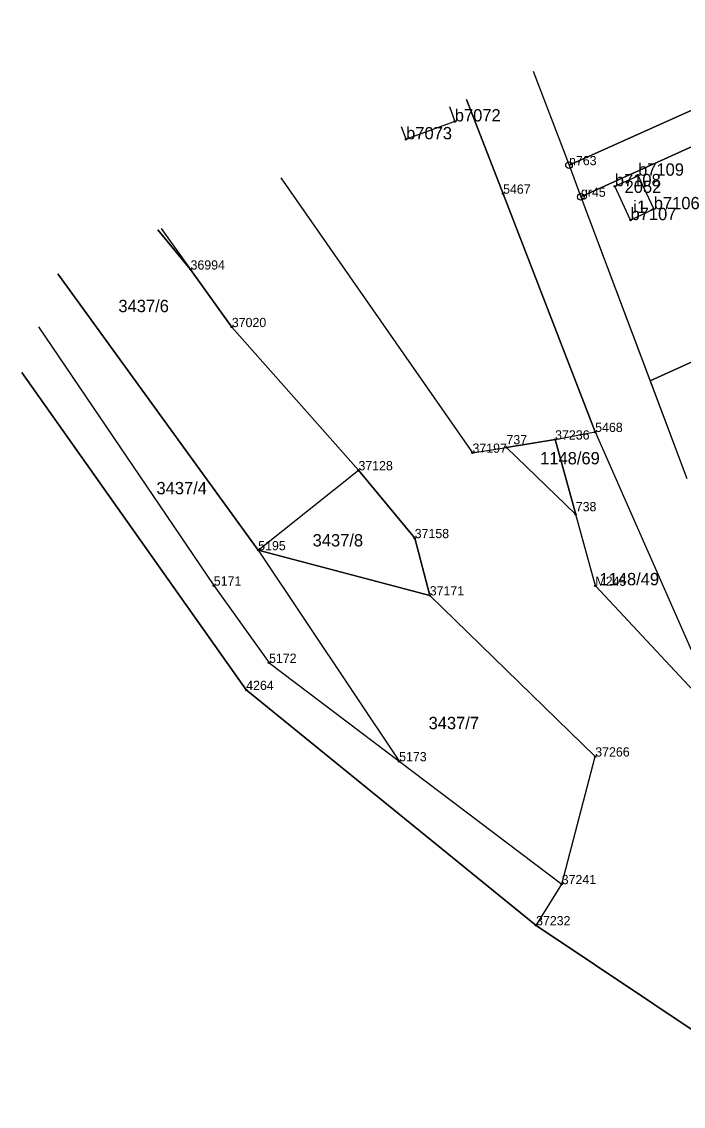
# Model space of a CAD drawing. Extents: x 7492083 to 7492670, y 5466693 to 5467065.
# Drawn here: x 7492083.3 to 7492163.8, y 5466933.4 to 5467065.4 of the extents above; entities that cross this region are included whole.
import ezdxf

# ---------------------------------------------------------------- set-up
doc = ezdxf.new("R2010")
doc.units = 0
for name, color, linetype in [('202-punkt graniczny', 7, 'Continuous'), ('202-punkt graniczny-Atr103', 7, 'Continuous'), ('203-punkt graniczny', 7, 'Continuous'), ('203-punkt graniczny-Atr103', 7, 'Continuous'), ('211-numer działki ewidencyjnej', 7, 'Continuous'), ('217-kontur klasyfikacyjny', 7, 'Continuous'), ('218-kontur użytku gruntowego', 7, 'Continuous'), ('219-działka ewidencyjna', 7, 'Continuous'), ('312-budynek ewidencyjny', 7, 'Continuous'), ('312-oznaczenie budynku ewidencyjnego', 7, 'Continuous'), ('312-oznaczenie budynku ewidencyjnego-Atr117', 7, 'Continuous'), ('Punkt budynku', 7, 'Continuous'), ('Punkt budynku-Atr103', 7, 'Continuous')]:
    doc.layers.add(name, color=color, linetype=linetype)

# ---------------------------------------------------------------- blocks, each defined once
blk = doc.blocks.new('203')
blk.add_circle((0, 0), 0.09)
blk = doc.blocks.new('202')
blk.add_circle((0, 0), 0.4)
blk = doc.blocks.new('PUNKTBUD')
blk.add_circle((0, 0), 0.09)

msp = doc.modelspace()

# ---------------------------------------------------------------- linework, layer by layer
at = {"layer": '217-kontur klasyfikacyjny'}
for points in [[(7492188.79, 5467065.38), (7492149.89, 5467047.92)], [(7492151.34, 5467044.08), (7492178.86, 5467056.54)], [(7492149.89, 5467047.92), (7492151.34, 5467044.08)], [(7492188.7, 5467034.81), (7492159.74, 5467021.69)], [(7492159.74, 5467021.69), (7492164.2, 5467009.8)]]:
    msp.add_lwpolyline(points, dxfattribs=at)
at = {"layer": '218-kontur użytku gruntowego'}
for points in [[(7492149.89, 5467047.92), (7492188.79, 5467065.38)], [(7492145.51, 5467059.36), (7492149.89, 5467047.92)], [(7492178.86, 5467056.54), (7492151.34, 5467044.08)], [(7492141.87, 5467044.45), (7492137.41, 5467055.93)], [(7492149.89, 5467047.92), (7492151.34, 5467044.08)], [(7492114.86, 5467046.38), (7492138.15, 5467012.93)], [(7492153.07, 5467015.46), (7492141.87, 5467044.45)], [(7492151.34, 5467044.08), (7492159.74, 5467021.69)], [(7492103.86, 5467035.22), (7492099.9, 5467040.05)], [(7492112.09, 5467001.07), (7492087.71, 5467034.69)], [(7492108.88, 5467028.22), (7492103.86, 5467035.22)], [(7492159.74, 5467021.69), (7492188.7, 5467034.81)], [(7492085.36, 5467028.26), (7492106.69, 5466996.76)], [(7492124.28, 5467010.8), (7492108.88, 5467028.22)], [(7492110.63, 5466984.07), (7492083.33, 5467022.7)], [(7492159.74, 5467021.69), (7492164.2, 5467009.8)], [(7492142.28, 5467013.59), (7492148.2, 5467014.54)], [(7492148.2, 5467014.54), (7492153.07, 5467015.46)], [(7492150.71, 5467005.43), (7492148.2, 5467014.54)], [(7492138.15, 5467012.93), (7492142.28, 5467013.59)], [(7492131.12, 5467002.54), (7492124.28, 5467010.8)], [(7492153.1, 5466996.74), (7492150.71, 5467005.43)], [(7492132.95, 5466995.57), (7492131.12, 5467002.54)], [(7492132.95, 5466995.57), (7492112.09, 5467001.07)], [(7492106.69, 5466996.76), (7492113.41, 5466987.37)], [(7492175.28, 5466972.96), (7492153.1, 5466996.74)], [(7492153.08, 5466975.97), (7492132.95, 5466995.57)], [(7492113.41, 5466987.37), (7492129.23, 5466975.39)], [(7492145.88, 5466955.43), (7492110.63, 5466984.07)], [(7492149, 5466960.44), (7492153.08, 5466975.97)], [(7492129.23, 5466975.39), (7492149, 5466960.44)], [(7492145.88, 5466955.43), (7492149, 5466960.44)], [(7492203.36, 5466916.98), (7492145.88, 5466955.43)]]:
    msp.add_lwpolyline(points, dxfattribs=at)
at = {"layer": '219-działka ewidencyjna'}
for points in [[(7492149.89, 5467047.92), (7492188.79, 5467065.38)], [(7492145.51, 5467059.36), (7492149.89, 5467047.92)], [(7492151.34, 5467044.08), (7492178.86, 5467056.54)], [(7492137.41, 5467055.93), (7492141.87, 5467044.45)], [(7492149.89, 5467047.92), (7492151.34, 5467044.08)], [(7492114.86, 5467046.38), (7492138.15, 5467012.93)], [(7492141.87, 5467044.45), (7492153.07, 5467015.46)], [(7492151.34, 5467044.08), (7492164.2, 5467009.8)], [(7492099.9, 5467040.05), (7492103.86, 5467035.22)], [(7492100.28, 5467040.21), (7492103.86, 5467035.22)], [(7492087.71, 5467034.69), (7492112.09, 5467001.07)], [(7492103.86, 5467035.22), (7492108.88, 5467028.22)], [(7492085.36, 5467028.26), (7492106.69, 5466996.76)], [(7492108.88, 5467028.22), (7492124.28, 5467010.8)], [(7492083.33, 5467022.7), (7492110.63, 5466984.07)], [(7492148.2, 5467014.54), (7492142.28, 5467013.59)], [(7492148.2, 5467014.54), (7492153.07, 5467015.46)], [(7492148.2, 5467014.54), (7492150.71, 5467005.43)], [(7492153.07, 5467015.46), (7492165.07, 5466988.24)], [(7492138.15, 5467012.93), (7492142.28, 5467013.59)], [(7492142.28, 5467013.59), (7492150.71, 5467005.43)], [(7492112.09, 5467001.07), (7492124.28, 5467010.8)], [(7492124.28, 5467010.8), (7492131.12, 5467002.54)], [(7492153.1, 5466996.74), (7492150.71, 5467005.43)], [(7492131.12, 5467002.54), (7492132.95, 5466995.57)], [(7492112.09, 5467001.07), (7492129.23, 5466975.39)], [(7492112.09, 5467001.07), (7492132.95, 5466995.57)], [(7492106.69, 5466996.76), (7492113.41, 5466987.37)], [(7492153.1, 5466996.74), (7492175.28, 5466972.96)], [(7492132.95, 5466995.57), (7492153.08, 5466975.97)], [(7492113.41, 5466987.37), (7492129.23, 5466975.39)], [(7492110.63, 5466984.07), (7492145.88, 5466955.43)], [(7492149, 5466960.44), (7492153.08, 5466975.97)], [(7492129.23, 5466975.39), (7492149, 5466960.44)], [(7492145.88, 5466955.43), (7492149, 5466960.44)], [(7492145.88, 5466955.43), (7492203.36, 5466916.98)]]:
    msp.add_lwpolyline(points, dxfattribs=at)
at = {"layer": '312-budynek ewidencyjny'}
for points in [[(7492135.34, 5467055.05), (7492136, 5467053.24)], [(7492130.08, 5467051.07), (7492129.53, 5467052.59)], [(7492136, 5467053.24), (7492130.08, 5467051.07)], [(7492155.46, 5467045.36), (7492158.29, 5467046.64)], [(7492158.29, 5467046.64), (7492160.2, 5467042.56)], [(7492157.37, 5467041.24), (7492155.46, 5467045.36)], [(7492160.2, 5467042.56), (7492157.37, 5467041.24)]]:
    msp.add_lwpolyline(points, dxfattribs=at)

# ---------------------------------------------------------------- block references
at = {"layer": '202-punkt graniczny'}
for p in [(7492149.89, 5467047.92), (7492151.34, 5467044.08)]:
    msp.add_blockref('202', p, dxfattribs=at)
at = {"layer": '203-punkt graniczny'}
for p in [(7492141.87, 5467044.45), (7492103.86, 5467035.22), (7492108.88, 5467028.22), (7492153.07, 5467015.46), (7492148.2, 5467014.54), (7492138.15, 5467012.93), (7492142.28, 5467013.59), (7492124.28, 5467010.8), (7492150.71, 5467005.43), (7492131.12, 5467002.54), (7492112.09, 5467001.07), (7492106.69, 5466996.76), (7492153.1, 5466996.74), (7492132.95, 5466995.57), (7492113.41, 5466987.37), (7492110.63, 5466984.07), (7492153.08, 5466975.97), (7492129.23, 5466975.39), (7492149, 5466960.44), (7492145.88, 5466955.43)]:
    msp.add_blockref('203', p, dxfattribs=at)
at = {"layer": 'Punkt budynku'}
for p in [(7492136, 5467053.24), (7492130.08, 5467051.07), (7492158.29, 5467046.64), (7492155.46, 5467045.36), (7492160.2, 5467042.56), (7492157.37, 5467041.24)]:
    msp.add_blockref('PUNKTBUD', p, dxfattribs=at)

# ---------------------------------------------------------------- texts
at = {"layer": '202-punkt graniczny-Atr103'}
for s, p in [('n763', (7492149.89, 5467047.92)), ('gr45', (7492151.34, 5467044.08))]:
    msp.add_text(s, height=1.125, dxfattribs=at).set_placement(p)
at = {"layer": '203-punkt graniczny-Atr103'}
for s, p in [('5467', (7492141.87, 5467044.45)), ('36994', (7492103.86, 5467035.22)), ('37020', (7492108.88, 5467028.22)), ('37236', (7492148.2, 5467014.54)), ('5468', (7492153.07, 5467015.46)), ('737', (7492142.28, 5467013.96)), ('37197', (7492138.15, 5467012.93)), ('37128', (7492124.28, 5467010.8)), ('738', (7492150.71, 5467005.81)), ('37158', (7492131.12, 5467002.54)), ('5195', (7492112.09, 5467001.07)), ('5171', (7492106.69, 5466996.76)), ('M245', (7492153.1, 5466996.74)), ('37171', (7492132.95, 5466995.57)), ('5172', (7492113.41, 5466987.37)), ('4264', (7492110.63, 5466984.07)), ('5173', (7492129.23, 5466975.39)), ('37266', (7492153.08, 5466975.97)), ('37241', (7492149, 5466960.44)), ('37232', (7492145.88, 5466955.43))]:
    msp.add_text(s, height=1.125, dxfattribs=at).set_placement(p)
at = {"layer": '211-numer działki ewidencyjnej'}
for s, p in [('3437/6', (7492095.09, 5467030.04)), ('1148/69', (7492146.38, 5467011.52)), ('3437/4', (7492099.72, 5467007.88)), ('3437/8', (7492118.71, 5467001.53)), ('1148/49', (7492153.59, 5466996.81)), ('3437/7', (7492132.81, 5466979.3))]:
    msp.add_text(s, height=1.5, dxfattribs=at).set_placement(p)
at = {"layer": '312-oznaczenie budynku ewidencyjnego'}
msp.add_text('2052', height=1.5, dxfattribs=at).set_placement((7492156.65, 5467044.55))
at = {"layer": '312-oznaczenie budynku ewidencyjnego-Atr117'}
msp.add_text('i1', height=1.5, dxfattribs=at).set_placement((7492157.7, 5467042.12))
at = {"layer": 'Punkt budynku-Atr103'}
for s, p in [('b7072', (7492136, 5467053.24)), ('b7073', (7492130.08, 5467051.07)), ('b7109', (7492158.29, 5467046.64)), ('b7108', (7492155.46, 5467045.36)), ('b7106', (7492160.2, 5467042.56)), ('b7107', (7492157.37, 5467041.24))]:
    msp.add_text(s, height=1.5, dxfattribs=at).set_placement(p)

doc.saveas('drawing.dxf')
